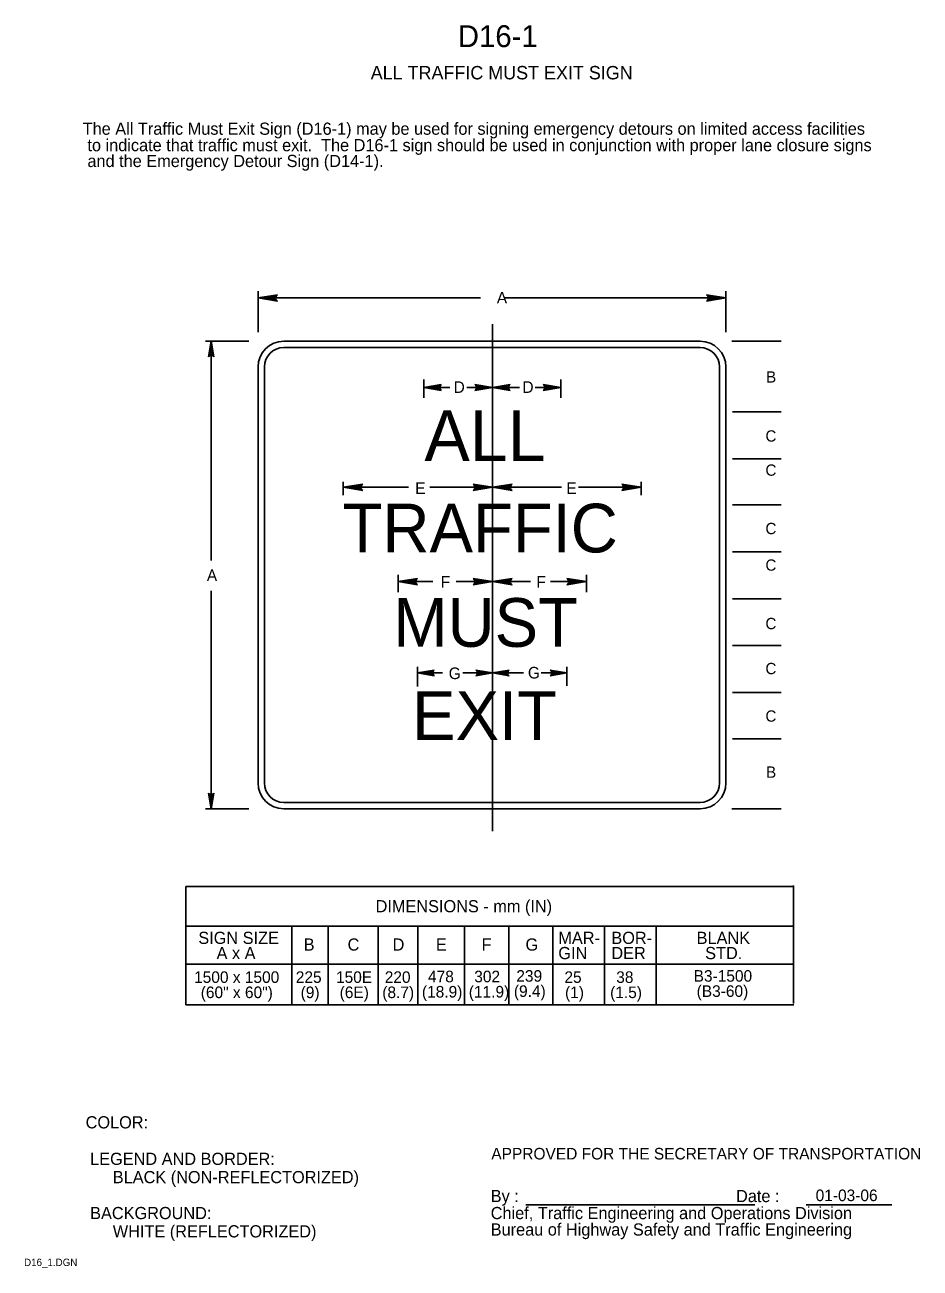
# Model space of a CAD drawing. Extents: x 0.013 to 0.196, y 0.004 to 0.259.
import ezdxf

# ---------------------------------------------------------------- set-up
doc = ezdxf.new("R2010")
doc.units = 0
for name, color, linetype in [('1', 7, 'Continuous'), ('3', 7, 'Continuous'), ('4', 7, 'Continuous')]:
    doc.layers.add(name, color=color, linetype=linetype)

# ---------------------------------------------------------------- blocks, each defined once
blk = doc.blocks.new('RARROW')
at = {"layer": '3'}
for p, q in [((-2.156, 0.285), (-2.2665, 0.384625)), ((-2.2665, 0.384625), (0, 0)), ((0, 0), (-2.2665, -0.379125)), ((-2.156, 0.285), (-2.075625, 0.12075)), ((0, 0), (-2.156, 0.285)), ((-2.14975, -0.2705), (0, 0)), ((-2.075625, 0.12075), (0, 0)), ((0, 0), (-2.074, -0.108)), ((-2.2665, -0.379125), (-2.14975, -0.2705)), ((-2.074, -0.108), (-2.14975, -0.2705))]:
    blk.add_line(p, q, dxfattribs=at)

msp = doc.modelspace()

# ---------------------------------------------------------------- linework, layer by layer
at = {"layer": '1'}
for p, q in [((0.10862, 0.19775), (0.10862, 0.09362)), ((0.11544, 0.01695), (0.16242, 0.01695)), ((0.17295, 0.01695), (0.19056, 0.01695))]:
    msp.add_line(p, q, dxfattribs=at)
at = {"layer": '3'}
for p, q in [((0.0605, 0.19612), (0.0605, 0.2045)), ((0.1565, 0.19612), (0.1565, 0.2045)), ((0.10612, 0.20312), (0.0605, 0.20312)), ((0.111, 0.20312), (0.1565, 0.20312)), ((0.05863, 0.19425), (0.04975, 0.19425)), ((0.05088, 0.14925), (0.05088, 0.19425)), ((0.0658, 0.19425), (0.1512, 0.19425)), ((0.15775, 0.19425), (0.16787, 0.19425)), ((0.0658, 0.19295), (0.1512, 0.19295)), ((0.0605, 0.18895), (0.0605, 0.10355)), ((0.0605, 0.10355), (0.0605, 0.18895)), ((0.0605, 0.10355), (0.0605, 0.18895)), ((0.0618, 0.10355), (0.0618, 0.18895)), ((0.1552, 0.18895), (0.1552, 0.10355)), ((0.1565, 0.18895), (0.1565, 0.10355)), ((0.0945, 0.18263), (0.0945, 0.18638)), ((0.10862, 0.18263), (0.10862, 0.18638)), ((0.12262, 0.18263), (0.12262, 0.18638)), ((0.09988, 0.18475), (0.0945, 0.18475)), ((0.10862, 0.18475), (0.10338, 0.18475)), ((0.11413, 0.18475), (0.10862, 0.18475)), ((0.12262, 0.18475), (0.11738, 0.18475)), ((0.15788, 0.17975), (0.16787, 0.17975)), ((0.15788, 0.17012), (0.16787, 0.17012)), ((0.078, 0.16537), (0.078, 0.16262)), ((0.09137, 0.16425), (0.078, 0.16425)), ((0.09575, 0.16425), (0.10862, 0.16425)), ((0.10862, 0.16537), (0.10862, 0.16262)), ((0.12275, 0.16425), (0.10862, 0.16425)), ((0.12625, 0.16425), (0.13912, 0.16425)), ((0.13912, 0.16537), (0.13912, 0.16262)), ((0.15788, 0.16062), (0.16787, 0.16062)), ((0.15788, 0.151), (0.16787, 0.151)), ((0.08925, 0.14275), (0.08925, 0.14625)), ((0.10862, 0.14275), (0.10862, 0.14638)), ((0.12788, 0.14275), (0.12788, 0.14625)), ((0.05088, 0.143), (0.05088, 0.09825)), ((0.08925, 0.14488), (0.09638, 0.14488)), ((0.10113, 0.14488), (0.10862, 0.14488)), ((0.11638, 0.14488), (0.10862, 0.14488)), ((0.12788, 0.14488), (0.1205, 0.14488)), ((0.15788, 0.14138), (0.16787, 0.14138)), ((0.15788, 0.13175), (0.16787, 0.13175)), ((0.09325, 0.12337), (0.09325, 0.12738)), ((0.09325, 0.12613), (0.09838, 0.12613)), ((0.1025, 0.12613), (0.10862, 0.12613)), ((0.10862, 0.12375), (0.10862, 0.12738)), ((0.115, 0.12613), (0.10862, 0.12613)), ((0.12387, 0.12613), (0.11863, 0.12613)), ((0.12387, 0.1235), (0.12387, 0.12738)), ((0.15788, 0.12212), (0.16787, 0.12212)), ((0.15788, 0.11263), (0.16787, 0.11263)), ((0.1512, 0.09955), (0.0658, 0.09955)), ((0.05863, 0.09825), (0.04975, 0.09825)), ((0.1512, 0.09825), (0.0658, 0.09825)), ((0.15775, 0.09825), (0.16787, 0.09825)), ((0.04567, 0.08226), (0.04567, 0.05801)), ((0.04567, 0.08226), (0.17041, 0.08226)), ((0.17037, 0.0825), (0.17037, 0.05825)), ((0.17041, 0.07413), (0.04591, 0.07413)), ((0.07492, 0.07423), (0.07492, 0.05801)), ((0.06742, 0.07398), (0.06742, 0.05801)), ((0.08517, 0.07398), (0.08517, 0.05801)), ((0.0933, 0.07398), (0.0933, 0.05801)), ((0.10287, 0.07398), (0.10287, 0.05801)), ((0.11198, 0.07398), (0.11198, 0.05801)), ((0.12098, 0.07398), (0.12098, 0.05801)), ((0.13159, 0.07398), (0.13159, 0.05801)), ((0.14221, 0.07398), (0.14221, 0.05801)), ((0.04561, 0.06638), (0.17041, 0.06638)), ((0.04567, 0.05801), (0.17041, 0.05801))]:
    msp.add_line(p, q, dxfattribs=at)
for centre, radius, start, end in [((0.0658, 0.18895), 0.0053, 90, 180), ((0.1512, 0.18895), 0.0053, 0, 90), ((0.0658, 0.18895), 0.004, 90, 180), ((0.1512, 0.18895), 0.004, 0, 90), ((0.0658, 0.10355), 0.0053, 180, 270), ((0.0658, 0.10355), 0.004, 180, 270), ((0.1512, 0.10355), 0.0053, 270, 0), ((0.1512, 0.10355), 0.004, 270, 0)]:
    msp.add_arc(centre, radius, start, end, dxfattribs=at)

# ---------------------------------------------------------------- block references
for p, xscale, yscale, rotation in [((0.0605, 0.20312), 0.0017647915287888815, 0.0017457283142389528, 180), ((0.05088, 0.19425), 0.0014118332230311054, 0.0013965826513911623, 90), ((0.0945, 0.18475), 0.0015883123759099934, 0.0015711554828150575, 180), ((0.10862, 0.18475), 0.0015883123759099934, 0.0015711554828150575, 180), ((0.078, 0.16425), 0.0017647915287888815, 0.0017457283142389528, 180), ((0.10862, 0.16425), 0.0017647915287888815, 0.0017457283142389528, 180), ((0.08925, 0.14488), 0.0017647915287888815, 0.0017457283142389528, 180), ((0.10862, 0.14488), 0.0017647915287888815, 0.0017457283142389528, 180), ((0.09325, 0.12613), 0.0015000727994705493, -0.0014838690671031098, 180), ((0.10862, 0.12613), 0.0015000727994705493, 0.0014838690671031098, 180), ((0.05088, 0.09825), 0.0014118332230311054, 0.0013965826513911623, -90)]:
    msp.add_blockref('RARROW', p, dxfattribs=dict(at, xscale=xscale, yscale=yscale, rotation=rotation))
for p, xscale, yscale in [((0.1565, 0.20312), 0.0017647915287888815, 0.0017457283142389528), ((0.10862, 0.18475), 0.0015883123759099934, -0.0015711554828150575), ((0.12262, 0.18475), 0.0015883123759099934, -0.0015711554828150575), ((0.10862, 0.16425), 0.0017647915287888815, 0.0017457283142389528), ((0.13912, 0.16425), 0.0017647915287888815, -0.0017457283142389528), ((0.10862, 0.14488), 0.0017647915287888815, 0.0017457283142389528), ((0.12788, 0.14488), 0.0017647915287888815, -0.0017457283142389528), ((0.10862, 0.12613), 0.0015000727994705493, 0.0014838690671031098), ((0.12387, 0.12613), 0.0015000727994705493, 0.0014838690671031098)]:
    msp.add_blockref('RARROW', p, dxfattribs=dict(at, xscale=xscale, yscale=yscale))

# ---------------------------------------------------------------- texts
at = {"layer": '1'}
for s, height, p in [('D16-1', 0.0045, (0.1015, 0.25462)), ('ALL TRAFFIC MUST EXIT SIGN', 0.0027503, (0.08363, 0.248)), ('     The All Traffic Must Exit Sign (D16-1) may be used for signing emergency detours on limited access facilities', 0.00249975, (0.01988, 0.23663)), ('to indicate that traffic must exit.  The D16-1 sign should be used in conjunction with proper lane closure signs', 0.00249975, (0.0255, 0.23325)), ('and the Emergency Detour Sign (D14-1).', 0.0024998, (0.0255, 0.23)), ('COLOR:', 0.0025, (0.02513, 0.03263)), ('APPROVED FOR THE SECRETARY OF TRANSPORTATION', 0.0023752, (0.10837, 0.02625)), (' LEGEND AND BORDER:', 0.0024998, (0.02513, 0.02513)), ('      BLACK (NON-REFLECTORIZED)', 0.0024998, (0.02513, 0.02138)), ('By :                                                Date :', 0.0024998, (0.10825, 0.0175)), (' BACKGROUND:', 0.0024998, (0.02513, 0.014)), ('Chief, Traffic Engineering and Operations Division', 0.0024998, (0.10825, 0.014)), ('      WHITE (REFLECTORIZED)', 0.0024998, (0.02513, 0.01025)), ('Bureau of Highway Safety and Traffic Engineering', 0.0024998, (0.10825, 0.01063)), ('D16_1.DGN', 0.0015, (0.0125, 0.00438))]:
    msp.add_text(s, height=height, dxfattribs=at).set_placement(p)
at = {"layer": '3'}
for s, height, p in [('A', 0.00237, (0.1095, 0.202)), ('B', 0.00232, (0.16475, 0.18575)), ('D', 0.00238, (0.10063, 0.18363)), ('D', 0.00238, (0.11475, 0.18363)), ('ALL', 0.010454, (0.09463, 0.16962)), ('C', 0.00232, (0.16462, 0.17363)), ('C', 0.00232, (0.16462, 0.16662)), ('E', 0.00238, (0.09275, 0.16287)), ('E', 0.00238, (0.12375, 0.16287)), ('TRAFFIC', 0.01, (0.07787, 0.15088)), ('C', 0.00232, (0.16462, 0.15463)), ('C', 0.00232, (0.16462, 0.14713)), ('A', 0.00238, (0.05, 0.145)), ('F', 0.00238, (0.098, 0.14363)), ('F', 0.00238, (0.11763, 0.14363)), ('MUST', 0.01, (0.08825, 0.1315)), ('C', 0.00232, (0.16462, 0.13512)), ('C', 0.00232, (0.16462, 0.12588)), ('G', 0.00238, (0.09963, 0.12487)), ('G', 0.00238, (0.11588, 0.125)), ('EXIT', 0.01, (0.09212, 0.11238)), ('C', 0.00232, (0.16462, 0.11613)), ('B', 0.00232, (0.16475, 0.10462)), ('DIMENSIONS - mm (IN)', 0.0024998, (0.08463, 0.077)), ('SIGN SIZE', 0.0025, (0.04825, 0.0705)), ('B', 0.0025, (0.06988, 0.06913)), ('C', 0.0025, (0.07888, 0.06913)), ('D', 0.0025, (0.08812, 0.06913)), ('E', 0.0025, (0.097, 0.06913)), ('F', 0.0025, (0.10637, 0.06913)), ('G', 0.0025, (0.11538, 0.06913)), ('MAR-', 0.0025, (0.12212, 0.0705)), ('BOR-', 0.0025, (0.133, 0.0705)), ('BLANK', 0.0025, (0.1505, 0.0705)), ('A x A', 0.0025, (0.052, 0.06738)), ('GIN', 0.0025, (0.12212, 0.06738)), ('DER', 0.0025, (0.133, 0.06738)), ('STD.', 0.0025, (0.15225, 0.06738)), ('1500 x 1500', 0.0023752, (0.04738, 0.0625)), ('225', 0.002375, (0.06825, 0.0625)), ('150E', 0.002375, (0.0765, 0.0625)), ('220', 0.002375, (0.0865, 0.0625)), ('478', 0.002375, (0.09538, 0.06263)), ('302', 0.002375, (0.10487, 0.06263)), ('239', 0.002375, (0.1135, 0.06275)), ('25', 0.002375, (0.12337, 0.0625)), ('38', 0.002375, (0.134, 0.0625)), ('B3-1500', 0.002375, (0.14988, 0.06275)), ('(60" x 60")', 0.0023752, (0.04875, 0.05938)), ('(9)', 0.002375, (0.06925, 0.05938)), ('(6E)', 0.002375, (0.07725, 0.05938)), ('(8.7)', 0.002375, (0.086, 0.05938)), ('(18.9)', 0.002375, (0.09413, 0.0595)), ('(11.9)', 0.002375, (0.10375, 0.0595)), ('(9.4)', 0.002375, (0.113, 0.05963)), ('(1)', 0.002375, (0.1235, 0.05938)), ('(1.5)', 0.002375, (0.13275, 0.05938)), ('(B3-60)', 0.002375, (0.1505, 0.05963))]:
    msp.add_text(s, height=height, dxfattribs=at).set_placement(p)
at = {"layer": '4'}
msp.add_text('01-03-06', height=0.002375, dxfattribs=at).set_placement((0.17492, 0.0177))

doc.saveas('drawing.dxf')
